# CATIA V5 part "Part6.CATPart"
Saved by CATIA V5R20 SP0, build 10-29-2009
Part number: 9FP1406M5
Revision: ANY
Definition: UNKNOWN
Nomenclature: 9FP1406M5
Source: Unknown
Bounding box of the stored display mesh (mm): x -6.727 to 6.727, y 0 to 6, z -6.9 to 6.9
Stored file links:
  C:\Users\Utente\Desktop\IO LAVORO\3D X SITO CF\CUMSA\3D files PW\pw081225\pw081225_injection\Part6.CATPart
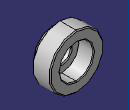
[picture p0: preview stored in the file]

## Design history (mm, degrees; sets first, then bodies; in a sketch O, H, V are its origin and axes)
Body1 "Chaflán1" (main body)
  Solid1: solid without history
